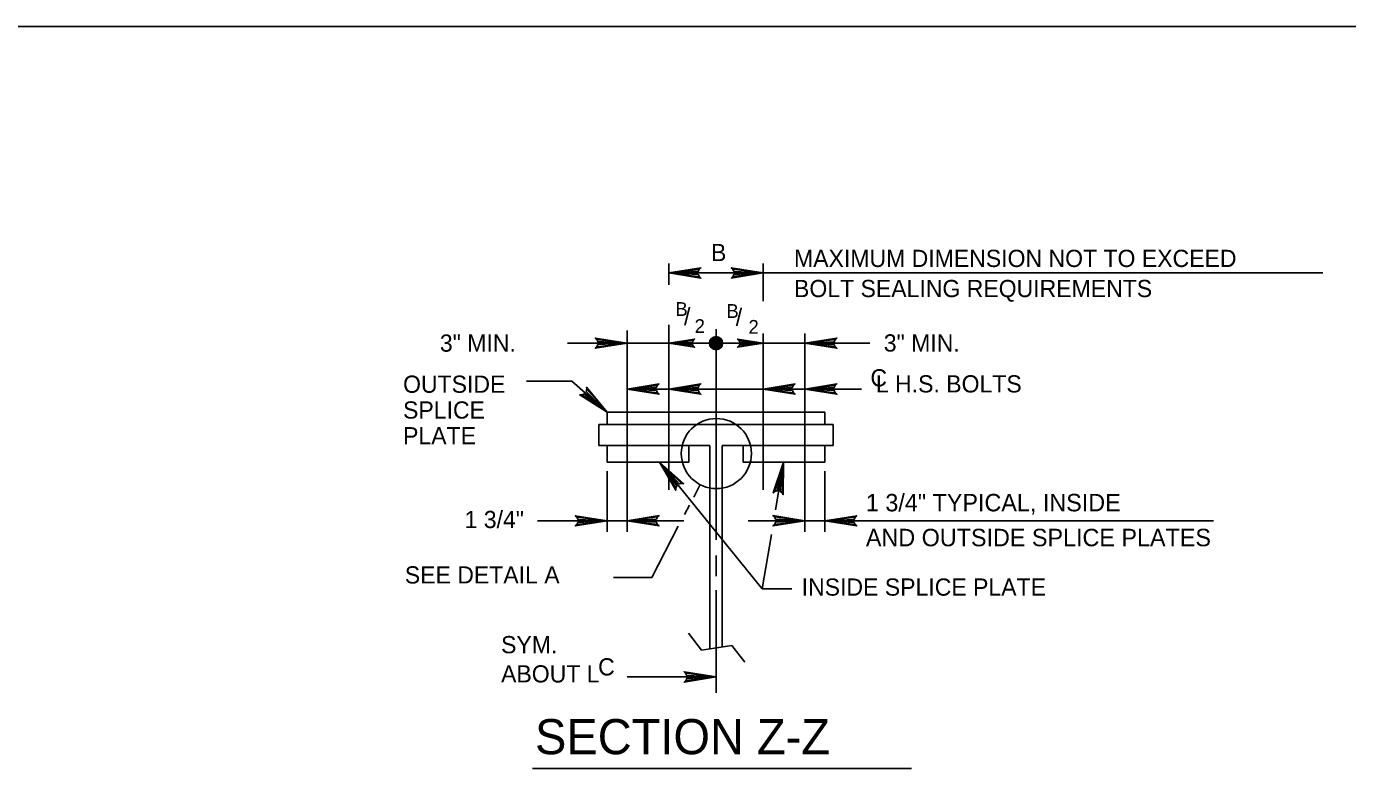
# Model space of a CAD drawing. Extents: x 638466 to 639375, y 297808 to 298996.
# Drawn here: x 638843.6 to 639092.2, y 298247.8 to 298387.5 of the extents above; entities that cross this region are included whole.
import ezdxf

# ---------------------------------------------------------------- set-up
doc = ezdxf.new("R2010")
doc.units = 0
for name, color, linetype in [('1', 7, 'Continuous'), ('2', 7, 'Continuous'), ('4', 7, 'Continuous')]:
    doc.layers.add(name, color=color, linetype=linetype)

msp = doc.modelspace()

# ---------------------------------------------------------------- linework, layer by layer
at = {"layer": '1'}
msp.add_line((639291.96, 298387.46), (638505.96, 298387.46), dxfattribs=at)
for points in [[(638970.23, 298340.32), (638970.01, 298340.73), (638964.51, 298341.04), (638970.23, 298340.32), (638970.52, 298340.07), (638964.51, 298341.04), (638970.01, 298341.31), (638970.21, 298341.72), (638964.51, 298341.04), (638970.52, 298341.99), (638970.21, 298341.72)], [(638976.51, 298341.76), (638976.72, 298341.34), (638982.23, 298341.04), (638976.51, 298341.76), (638976.22, 298342.01), (638982.23, 298341.04), (638976.72, 298340.77), (638976.52, 298340.36), (638982.23, 298341.04), (638976.22, 298340.09), (638976.52, 298340.36)], [(638950.91, 298328.54), (638951.12, 298328.13), (638956.63, 298327.83), (638950.91, 298328.54), (638950.62, 298328.79), (638956.63, 298327.83), (638951.13, 298327.56), (638950.93, 298327.14), (638956.63, 298327.83), (638950.62, 298326.87), (638950.93, 298327.14)], [(638969.08, 298327.25), (638968.91, 298327.58), (638964.51, 298327.83), (638969.08, 298327.25), (638969.32, 298327.05), (638964.51, 298327.83), (638968.91, 298328.04), (638969.07, 298328.37), (638964.51, 298327.83), (638969.32, 298328.59), (638969.07, 298328.37)], [(638977.65, 298328.4), (638977.82, 298328.07), (638982.23, 298327.83), (638977.65, 298328.4), (638977.42, 298328.6), (638982.23, 298327.83), (638977.82, 298327.61), (638977.66, 298327.28), (638982.23, 298327.83), (638977.42, 298327.06), (638977.66, 298327.28)], [(638995.82, 298327.11), (638995.61, 298327.52), (638990.1, 298327.83), (638995.82, 298327.11), (638996.12, 298326.86), (638990.1, 298327.83), (638995.61, 298328.1), (638995.81, 298328.5), (638990.1, 298327.83), (638996.12, 298328.78), (638995.81, 298328.5)], [(638962.35, 298318.48), (638962.14, 298318.89), (638956.63, 298319.2), (638962.35, 298318.48), (638962.64, 298318.23), (638956.63, 298319.2), (638962.13, 298319.47), (638962.34, 298319.88), (638956.63, 298319.2), (638962.64, 298320.15), (638962.34, 298319.88)], [(638970.23, 298318.48), (638970.01, 298318.89), (638964.51, 298319.2), (638970.23, 298318.48), (638970.52, 298318.23), (638964.51, 298319.2), (638970.01, 298319.47), (638970.21, 298319.88), (638964.51, 298319.2), (638970.52, 298320.15), (638970.21, 298319.88)], [(638987.95, 298318.48), (638987.74, 298318.89), (638982.23, 298319.2), (638987.95, 298318.48), (638988.24, 298318.23), (638982.23, 298319.2), (638987.73, 298319.47), (638987.93, 298319.88), (638982.23, 298319.2), (638988.24, 298320.15), (638987.93, 298319.88)], [(638995.82, 298318.48), (638995.61, 298318.89), (638990.1, 298319.2), (638995.82, 298318.48), (638996.12, 298318.23), (638990.1, 298319.2), (638995.61, 298319.47), (638995.81, 298319.88), (638990.1, 298319.2), (638996.12, 298320.15), (638995.81, 298319.88)], [(638949.04, 298319.16), (638948.93, 298318.71), (638952.89, 298314.87), (638949.04, 298319.16), (638948.98, 298319.54), (638952.89, 298314.87), (638948.56, 298318.27), (638948.14, 298318.09), (638952.89, 298314.87), (638947.72, 298318.09), (638948.14, 298318.09)], [(638965.8, 298300.54), (638965.99, 298300.96), (638962.74, 298305.42), (638965.8, 298300.54), (638965.79, 298300.15), (638962.74, 298305.42), (638966.43, 298301.33), (638966.88, 298301.44), (638962.74, 298305.42), (638967.28, 298301.37), (638966.88, 298301.44)], [(638984.43, 298299.9), (638984.87, 298300.04), (638986.1, 298305.42), (638984.43, 298299.9), (638984.13, 298299.65), (638986.1, 298305.42), (638985.44, 298299.95), (638985.81, 298299.68), (638986.1, 298305.42), (638986.03, 298299.33), (638985.81, 298299.68)], [(638947.17, 298293.68), (638947.38, 298294.09), (638952.89, 298294.39), (638947.17, 298293.68), (638946.88, 298293.42), (638952.89, 298294.39), (638947.39, 298294.66), (638947.19, 298295.07), (638952.89, 298294.39), (638946.88, 298295.35), (638947.19, 298295.07)], [(638962.35, 298295.11), (638962.14, 298294.7), (638956.63, 298294.39), (638962.35, 298295.11), (638962.64, 298295.36), (638956.63, 298294.39), (638962.13, 298294.12), (638962.34, 298293.71), (638956.63, 298294.39), (638962.64, 298293.44), (638962.34, 298293.71)], [(638984.38, 298295.11), (638984.59, 298294.7), (638990.1, 298294.39), (638984.38, 298295.11), (638984.09, 298295.36), (638990.1, 298294.39), (638984.6, 298294.12), (638984.4, 298293.71), (638990.1, 298294.39), (638984.09, 298293.44), (638984.4, 298293.71)], [(638999.56, 298293.68), (638999.35, 298294.09), (638993.84, 298294.39), (638999.56, 298293.68), (638999.86, 298293.42), (638993.84, 298294.39), (638999.35, 298294.66), (638999.55, 298295.07), (638993.84, 298294.39), (638999.86, 298295.35), (638999.55, 298295.07)], [(638967.65, 298265.71), (638967.86, 298265.3), (638973.37, 298265), (638967.65, 298265.71), (638967.35, 298265.97), (638973.37, 298265), (638967.86, 298264.72), (638967.66, 298264.31), (638973.37, 298265), (638967.35, 298264.04), (638967.66, 298264.31)]]:
    msp.add_lwpolyline(points, dxfattribs=at)
at = {"layer": '2'}
for p, q in [((638964.51, 298342.84), (638964.51, 298338.81)), ((638982.23, 298342.84), (638982.23, 298335.75)), ((638956.63, 298292.31), (638956.63, 298330.23)), ((638964.51, 298300.23), (638964.51, 298331.3)), ((638973.37, 298330.46), (638973.37, 298290.78)), ((638982.23, 298300.23), (638982.23, 298329.68)), ((638990.1, 298292.31), (638990.1, 298329.68)), ((638952.89, 298314.87), (638993.84, 298314.87)), ((638952.89, 298312.5), (638952.89, 298314.87)), ((638993.84, 298312.5), (638993.84, 298314.87)), ((638951.32, 298312.5), (638995.42, 298312.5)), ((638951.32, 298308.56), (638951.32, 298312.5)), ((638995.42, 298308.56), (638995.42, 298312.5)), ((638972.19, 298308.56), (638951.32, 298308.56)), ((638952.89, 298305.42), (638952.89, 298308.56)), ((638968.25, 298305.42), (638968.25, 298308.56)), ((638972.19, 298308.56), (638972.19, 298270.3)), ((638974.55, 298308.56), (638974.55, 298270.67)), ((638974.55, 298308.56), (638995.42, 298308.56)), ((638978.49, 298305.42), (638978.49, 298308.56)), ((638993.84, 298305.42), (638993.84, 298308.56)), ((638952.89, 298305.42), (638968.25, 298305.42)), ((638993.84, 298305.42), (638978.49, 298305.42)), ((638952.89, 298292.31), (638952.89, 298303.71)), ((638993.84, 298292.31), (638993.84, 298303.71)), ((638973.37, 298287.86), (638973.37, 298283.97)), ((638973.37, 298261.99), (638973.37, 298281.33)), ((638968.19, 298273.27), (638970.66, 298270.06)), ((638970.66, 298270.06), (638976.33, 298270.95)), ((638976.33, 298270.95), (638978.79, 298267.75))]:
    msp.add_line(p, q, dxfattribs=at)
at = {"layer": '4'}
for p, q in [((639087.61, 298341.04), (638964.51, 298341.04)), ((638945.38, 298327.83), (638964.51, 298327.83)), ((638982.23, 298327.83), (638964.51, 298327.83)), ((639002.31, 298327.83), (638982.23, 298327.83)), ((638937.71, 298320.66), (638946.22, 298320.66)), ((638946.22, 298320.66), (638952.89, 298314.87)), ((639000.78, 298319.2), (638956.63, 298319.2)), ((638982.05, 298281.61), (638962.74, 298305.42)), ((638986.1, 298305.42), (638984.58, 298296.48)), ((638969.16, 298298.84), (638970.39, 298301.2)), ((638967.45, 298295.55), (638968.38, 298297.33)), ((638939.75, 298294.39), (638952.89, 298294.39)), ((638956.63, 298294.39), (638952.89, 298294.39)), ((638967.29, 298294.39), (638956.63, 298294.39)), ((638961.28, 298283.75), (638966.27, 298293.36)), ((638979.44, 298294.39), (638990.1, 298294.39)), ((638990.1, 298294.39), (638993.84, 298294.39)), ((639067.04, 298294.39), (638993.84, 298294.39)), ((638982.05, 298281.61), (638983.78, 298291.8)), ((638961.28, 298283.75), (638954.06, 298283.75)), ((638982.05, 298281.61), (638987.63, 298281.61)), ((638973.37, 298265), (638956.63, 298265)), ((639010.18, 298247.75), (638938.83, 298247.75))]:
    msp.add_line(p, q, dxfattribs=at)
for centre, radius in [((638973.37, 298327.83), 1.24), ((638973.37, 298327.83), 1.15), ((638973.37, 298327.83), 1.06), ((638973.37, 298327.83), 0.974), ((638973.37, 298327.83), 0.886), ((638973.37, 298327.83), 0.798), ((638973.37, 298327.83), 0.71), ((638973.37, 298327.83), 0.622), ((638973.37, 298327.83), 0.534), ((638973.37, 298327.83), 0.446), ((638973.37, 298327.83), 0.359), ((638973.37, 298327.83), 0.271), ((638973.37, 298327.83), 0.183), ((638973.37, 298327.83), 0.0949), ((638973.43, 298307.05), 6.6)]:
    msp.add_circle(centre, radius, dxfattribs=at)

# ---------------------------------------------------------------- texts
for s, height, p in [('B', 3.24, (638972.42, 298343.27)), ('MAXIMUM DIMENSION NOT TO EXCEED', 3.24, (638988.05, 298342.17)), ('BOLT SEALING REQUIREMENTS', 3.24, (638988.05, 298336.5)), ('B', 2.59, (638965.72, 298332.96)), ('B', 2.59, (638975.33, 298332.59)), ('/', 3.24, (638967.34, 298331.23)), ('2', 2.59, (638969.35, 298329.75)), ('/', 3.24, (638977.08, 298331.09)), ('2', 2.59, (638979.48, 298329.6)), ('3" MIN.', 3.24, (638921.39, 298326.23)), ('3" MIN.', 3.24, (639004.95, 298326.25)), ('C', 3.24, (639002.43, 298319.69)), ('OUTSIDE', 3.24, (638914.46, 298318.49)), ('L H.S. BOLTS', 3.24, (639003.46, 298318.55)), ('SPLICE', 3.24, (638914.46, 298313.63)), ('PLATE', 3.24, (638914.46, 298308.78)), ('1 3/4" TYPICAL, INSIDE', 3.2858, (639001.58, 298296.17)), ('1 3/4"', 3.24, (638926.04, 298293.02)), ('AND OUTSIDE SPLICE PLATES', 3.2858, (639001.58, 298289.6)), ('SEE DETAIL A', 3.24, (638914.79, 298282.59)), ('INSIDE SPLICE PLATE', 3.24, (638989.49, 298280.3)), ('SYM.', 3.24, (638932.91, 298269.46)), ('C', 3.24, (638951.17, 298265.28)), ('ABOUT L', 3.24, (638932.91, 298263.96)), ('SECTION Z-Z', 6.615, (638939.3, 298250.45))]:
    msp.add_text(s, height=height, dxfattribs=at).set_placement(p)

doc.saveas('drawing.dxf')
